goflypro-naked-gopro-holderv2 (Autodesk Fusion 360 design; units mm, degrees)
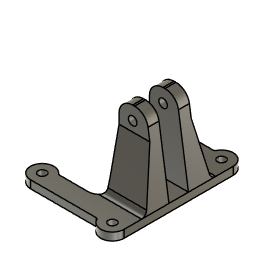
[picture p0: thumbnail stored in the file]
sketch "Skizze1" plane through (0, 0, 0) normal (0, 0, 1) x axis (1, 0, 0)
  line L1 (7.1716, 3) -> (-10, 3)
  line L2 (7.1716, -27) -> (-10, -27)
  line L3 (3, -6.7) -> (13, -6.7)
  line L4 (3, -9.5) -> (13, -9.5)
  line L5 (3, -14.5) -> (13, -14.5)
  line L6 (13, -17.3) -> (3, -17.3)
  line L7 (3, -4.75) -> (3, -19.25)
  line L8 (0.0016, -1.75) -> (-7.5633, -1.75)
  line L9 (0.0004, -22.25) -> (-7.5633, -22.25)
  line L10 (13, -26) -> (13, 2)
  circle C1 centre (-10, 0) radius 1.05
  circle C2 centre (10, 2) radius 1.05
  circle C3 centre (-10, -24) radius 1.05
  circle C4 centre (10, -26) radius 1.05
  circle C5 centre (-10, -24) radius 3
  circle C6 centre (10, -26) radius 3
  circle C7 centre (-10, 0) radius 3
  circle C8 centre (10, 2) radius 3
  arc A1 centre (0, -4.75) radius 3 clockwise from (-0.0016, -1.75) to (3, -4.75)
  arc A2 centre (0, -19.25) radius 3 clockwise from (3, -19.25) to (-0.0004, -22.25)
  point P10 (-10, 3)
  point P11 (7.1716, 3)
  point P12 (-10, -27)
  point P13 (7.1716, -27)
  point P22 (-7.5633, -22.25)
  point P23 (-7.5633, -1.75)
  point P26 (-0.0016, -1.75)
  point P28 (0.0016, -1.75)
  point P30 (-0.0004, -22.25)
  point P31 (0.0004, -22.25)
  point P32 (13, 2)
  point P20 (13, -14.5)
  point P15 (13, -17.3)
  point P19 (13, -9.5)
  point P18 (13, -6.7)
  concentric C3 C5
  concentric C4 C6
  concentric C1 C7
  concentric C2 C8
  coincident C7 P10
  coincident C8 P11
  tangent C7 L1
  horizontal L1
  coincident C5 P12
  coincident C6 P13
  tangent C5 L2
  horizontal L2
  horizontal L3
  horizontal L6
  horizontal L8
  horizontal L9
  coincident C5 P22
  coincident C7 P23
  tangent L7 A1
  tangent L7 A2
  horizontal L5
  horizontal L4
  coincident L8 P26
  coincident A1 P28
  coincident L9 P30
  coincident A2 P31
  coincident C8 P32
  tangent C8 L10
  perpendicular L3 L10
  coincident P20 L10
  coincident P15 L10
  coincident P19 L10
  dimension "d3" diameter C1 = 2.1
  dimension "d4" diameter C2 = 2.1
  dimension "d11" diameter C3 = 2.1
  dimension "d12" diameter C4 = 2.1
  dimension "d13" diameter C5 = 6
  dimension "d14" diameter C6 = 6
  dimension "d15" diameter C7 = 6
  dimension "d16" diameter C8 = 6
  dimension "d74" distance P15 P18 = 10.6
extrude "Extrusion3" new body sketch "Skizze1" along normal blind 2 bodies "GoFlyPro - naked-gopro-holderV2"
extrude "Extrusion8" add sketch "Skizze1" profile of L3 L4 L5 L6 L7 L10 along normal blind 22
sketch "Skizze7" plane through (0, -6.7, 0) normal (0, 1, 0) x axis (-1, 0, 0)
  line L1 (-3, 2) -> (-13, 2)
  line L2 (-3, 22) -> (-3, 2)
  line L3 (-13, 22) -> (-3, 22)
  line L4 (-13, 2) -> (-13, 22)
  circle C1 centre (-6.5, 18.5) radius 2.1
  circle C2 centre (-6.5, 18.5) radius 1.1
  concentric C1 C2
  dimension "d77" diameter C2 = 2.2
  dimension "d78" diameter C1 = 4.2
extrude "Extrusion9" cut sketch "Skizze7" profile of C2 against normal blind 11
extrude "Extrusion10" cut sketch "Skizze7" profile of C1 C2 against normal blind 0.5
chamfer "Fase1" distance 3 distance 20
chamfer "Fase2" distance 3 distance 14
fillet "Abrundung16" radius 3.5
fillet "Abrundung17" radius 1.5
fillet "Abrundung18" radius 0.5
fillet "Abrundung19" radius 0.5
named bodies: "GoFlyPro - naked-gopro-holderV2"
